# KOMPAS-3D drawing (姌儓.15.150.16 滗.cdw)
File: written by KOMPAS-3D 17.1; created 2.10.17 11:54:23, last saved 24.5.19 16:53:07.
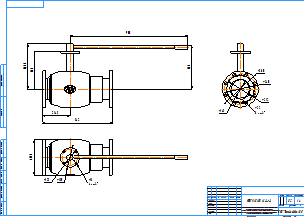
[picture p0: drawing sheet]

Sheet 1: A2, landscape

Title block, sheet 1: name: КШГИ.15.150.16 ф/ф; mass: 82; sheets: 1; organisation: ООО "Торговый дом АДЛ"; sheet format: A2; stored path: C:\Users\kka\KOMPAS_Work\КШП.ГИ\Ду150\КШГИ.15.150.16 ФФ ГЧ _ Кран шаровой БИВАЛ Ду150 Ру1,6 МПа полнопроходной газовый изолирующий фланцевый Габаритный чертеж.cdw

Views: Вид 1, Проекционный вид 2, Проекционный вид 3
Referenced files in C:\Users\kka\KOMPAS_Work\КШП.ГИ\Ду150\: КШП.ГИ.150.00.00-00.16 СБ.a3d, КШП.ГИ.150.00.00-00.16 СБ.a3d!КШП.ГИ.150.00.00-00.16!Деталь (локальная) 5.m3d, КШП.ГИ.150.00.00-00.16 СБ.a3d!КШП.ГИ.150.00.00-00.16!Деталь (локальная) 4.m3d, Фланец 1-150-16 Ст.20 ГОСТ 12820-80.m3d
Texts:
  kka
  adl
  Рама для чертежей
  Лит-Масса-Масштаб
  Материал-Предприятие
  Масштаб
  Изм.
  Лист
  № докум.
  Подп.
  Дата
  Лит.
  Разраб.
  Пров.
  Т.контр.
  Листов
  Внимание! Данный продукт является объектом авторского права ООО «Торговый Дом АДЛ».
  Запрещается изменение, копирование, распространение
  (в том числе путем копирования на другие сайты и ресурсы в Интернете)
  или любое иное использование информации и объектов без предварительного
  согласия правообладателя (ООО «Торговый Дом АДЛ»).
  Н.контр.
  Утв.
  Изменение
  Номер документа
  Подпись
  Обозначение документа
  Наименование изделия
  Масса изделия по ГОСТ 2.109-73
  Порядковый номер листа
  Общее количество листов в документе
  Характер работы, выполненной лицом, подписавшим документ
  Наименование или индекс предприятия, выпускающего документ
  Инв. № подл.
  Подп. и дата
  Взам. инв. №
  Инв. № дубл.
  Инвентарный номер подлинника по ГОСТ 2.501-68
  Подпись принявшего подлинник в отдел технической документации
  Инвентарный номер подлинника, взамен которого выпущен данный подлинник
  Инвентарный номер дубликата по ГОСТ 2.502-68
  Подпись принявшего дубликат в отдел технической документации
  Справ. №
  Перв. примен.
  Обозначение документа, взамен или на основании которого выпущен данный документ
  Обозначение документа, в котором впервые записан данный документ
  Подпись лица, копировавшего чертеж
  Обозначение формата листа
  !Рама для чертежа
Dimensions and other numbers on the sheet: 289; 349,5; 336; 900; 542; 214,5; 125; 150; 13; 4 отв.; 273; 145; 280; 240; 212; 22; 8 отв.; 1:4; 1; 82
